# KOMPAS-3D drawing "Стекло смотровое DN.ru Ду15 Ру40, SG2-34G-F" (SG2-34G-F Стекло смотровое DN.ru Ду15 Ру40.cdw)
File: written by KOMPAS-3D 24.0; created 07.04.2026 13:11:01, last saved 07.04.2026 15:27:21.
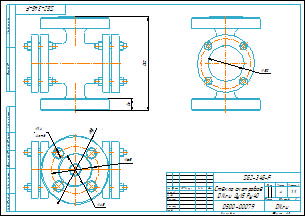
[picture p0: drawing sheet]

Document properties: Автор: Main; Форматы листов документа: A3; Полное имя файла: SG2-34G-F Стекло смотровое DN.ru Ду15 Ру40.m3d; Масса: 4; Наименование: Стекло смотровое DN.ru Ду15 Ру40; Количество листов документа: 1; Примечание: D500-00079

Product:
- Body: Тело 1  | qty 1
    Масса: 3.175709
- Part/product: Стекло смотровое DN.ru Ду15 Ру40  | designation SG2-34G-F
    Масса: 4
    Раздел спецификации: Прочие изделия
    Примечание: D500-00079

Views: Вид 1, Снизу, Проекционный вид 3
Referenced files in D:\DN.ru Аутсерс\Стекло смотровое DN.ru\Стекло смотровое DN.ru SG2-34G-F тип В ГОСТ 21836-2021 Ду100 Ру16, углеродистая сталь, фланцевое\: SG2-34G-F тип В Стекло смотровое DN.ru Ду100 Ру16.m3d, SG2-34G-F тип ВСтекло смотровое DN.ru Ду100 Ру16.cdw
Referenced files in D:\DN.ru Аутсерс\Стекло смотровое DN.ru\SG2-34G-F Стекло смотровое DN.ru Ду15 Ру40\: SG2-34G-F Стекло смотровое DN.ru Ду15 Ру40.m3d
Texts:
  SG2-34G-F
  Стекло смотровое
  DN.ru Ду15 Ру40
  Стекло смотровое DN.ru Ду15 Ру40
  SG2-34G-F Стекло смотровое DN.ru Ду15 Ру40
Dimensions and other numbers on the sheet: 0; 3; 2; 4; 130; 16; 50; 1:1; 1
